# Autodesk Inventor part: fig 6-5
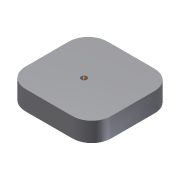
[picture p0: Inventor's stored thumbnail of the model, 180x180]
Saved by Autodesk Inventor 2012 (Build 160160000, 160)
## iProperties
Created: 2004-05
Part Number: fig 6-5
Document SubType Name: Modeling
Designer: CADCIM Technologies
Manufacturer: Standard
Standards Organization: Custom
Density: 1 g/cm^3
Material: Default
Author: CADCIM Technologies
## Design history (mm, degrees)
sketch "Sketch1"
  geometry: L1 (0, 0)-(44.293, 0); L2 (44.293, 0)-(44.293, 42.442); L3 (44.293, 42.442)-(0, 42.442); L4 (0, 42.442)-(0, 0)
  constraints: 8 end point, 2 parallel, 1 horizontal, 1 perpendicular
extrude "Extrusion1" new body sketch "Sketch1" distance "d0" = 10; taper "d1" = 0 deg
fillet "Fillet1" dims "d2" = 10
sketch "Sketch2"
  geometry: 1 further point
sketch "Sketch3"
  geometry: L1 (10, 42.442)-(34.293, 42.442) reference; L2 (0, 10)-(0, 32.442) reference; L3 (34.293, 0)-(10, 0) reference; L4 (44.293, 32.442)-(44.293, 10) reference; A1 r 10 centre (34.293, 32.442) between (44.293, 32.442) and (34.293, 42.442) reference; A2 r 10 centre (10, 32.442) between (10, 42.442) and (0, 32.442) reference; A3 r 10 centre (10, 10) between (0, 10) and (10, 0) reference; A4 r 10 centre (34.293, 10) between (34.293, 0) and (44.293, 10) reference; 1 further point
workaxis "Work Axis1"
  workpoint "Work Point1"
hole "Hole3" diameter "d24" = 3; stored, may be unused: countersink angle "d28" = 90 deg, drill point angle "d30" = 118 deg; dims "d22" = 10, "d23" = 10, "d25" = 6, "d26" = 4, "d27" = 2, "d29" = 8
body "Solid1"
